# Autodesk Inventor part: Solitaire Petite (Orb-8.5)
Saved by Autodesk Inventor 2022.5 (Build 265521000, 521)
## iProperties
Created: 2025-02
Part Number: Solitaire Petite (Orb-8.5)
Material: Generic
Document SubType Name: Modeling
Designer: AdminForWorker
Density: 1 g/cm^3
Appearance: Default
Title: Solitaire Petite (Orb-8.5)
Author: AdminForWorker
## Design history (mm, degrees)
feature "Orb-8.5"
body "Solid1"
